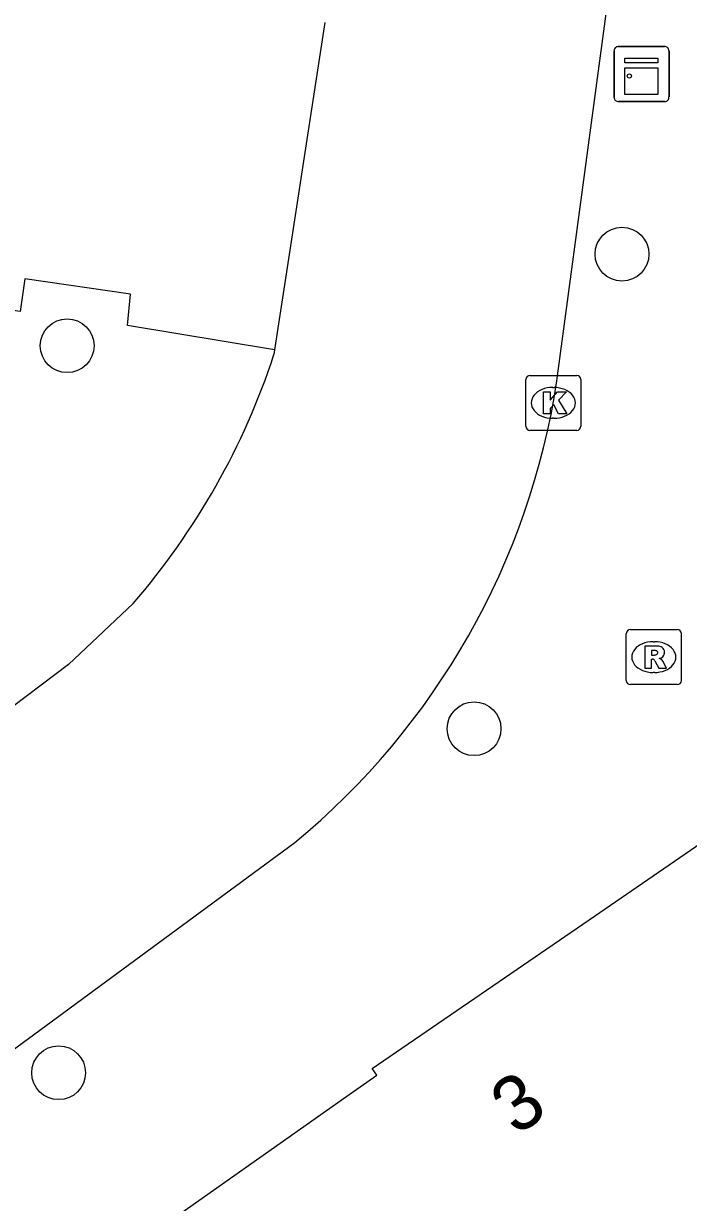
# Model space of a CAD drawing. Extents: x 160664 to 161506, y 382245 to 383288.
# Drawn here: x 160901.63 to 160913.72, y 383220.36 to 383241.8 of the extents above; entities that cross this region are included whole.
import ezdxf

# ---------------------------------------------------------------- set-up
doc = ezdxf.new("R2010")
doc.units = 0
for name, color, linetype in [('IMGEO_Boom', 7, 'Continuous'), ('IMGEO_Kast', 7, 'Continuous'), ('IMGEO_Kolk', 7, 'Continuous'), ('IMGEO_Pand', 7, 'Continuous'), ('IMGEO_Pand_nummerreeks', 7, 'Continuous'), ('IMGEO_Rijbaan_lokaal_gesloten', 7, 'Continuous'), ('IMGEO_Rijbaan_lokaal_open', 7, 'Continuous'), ('IMGEO_Rioolput', 7, 'Continuous')]:
    doc.layers.add(name, color=color, linetype=linetype)

msp = doc.modelspace()

# ---------------------------------------------------------------- linework, layer by layer
at = {"layer": 'IMGEO_Boom'}
for centre in [(160912.513, 383237.607), (160902.424, 383235.941), (160909.823, 383228.976), (160902.269, 383222.719)]:
    msp.add_circle(centre, 0.489, dxfattribs=at)
at = {"layer": 'IMGEO_Kast'}
for p, q in [((160912.443, 383241.382), (160913.284, 383241.382)), ((160913.284, 383241.382), (160912.443, 383241.382)), ((160913.368, 383241.307), (160913.368, 383240.466)), ((160913.368, 383240.466), (160913.368, 383241.307)), ((160912.368, 383240.457), (160912.368, 383241.298)), ((160912.368, 383241.298), (160912.368, 383240.457)), ((160913.293, 383240.382), (160912.452, 383240.382)), ((160912.452, 383240.382), (160913.293, 383240.382))]:
    msp.add_line(p, q, dxfattribs=at)
for points in [[(160912.563, 383241.172), (160913.163, 383241.172), (160913.163, 383241.087), (160912.563, 383241.087), (160912.563, 383241.172)], [(160912.563, 383240.997), (160913.163, 383240.997), (160913.163, 383240.508), (160912.563, 383240.508), (160912.563, 383240.997)]]:
    msp.add_lwpolyline(points, dxfattribs=at)
msp.add_circle((160912.647, 383240.846), 0.0377, dxfattribs=at)
for centre, start, end in [((160912.446, 383241.304), 92.4484, 184.2845), ((160912.446, 383241.304), 92.4484, 184.2845), ((160913.29, 383241.304), 2.4484, 94.2845), ((160913.29, 383241.304), 2.4484, 94.2845), ((160912.446, 383240.46), 182.4484, 274.2845), ((160912.446, 383240.46), 182.4484, 274.2845), ((160913.29, 383240.46), 272.4484, 4.2845), ((160913.29, 383240.46), 272.4484, 4.2845)]:
    msp.add_arc(centre, 0.0779, start, end, dxfattribs=at)
at = {"layer": 'IMGEO_Kolk'}
for p, q in [((160910.764, 383234.476), (160910.764, 383235.328)), ((160910.839, 383235.402), (160911.691, 383235.402)), ((160911.765, 383235.328), (160911.765, 383234.476)), ((160911.252, 383235.182), (160911.277, 383235.182)), ((160911.275, 383234.622), (160911.25, 383234.622)), ((160911.691, 383234.402), (160910.839, 383234.402))]:
    msp.add_line(p, q, dxfattribs=at)
for points in [[(160910.764, 383234.476), (160910.764, 383235.328)], [(160910.839, 383235.402), (160911.691, 383235.402)], [(160911.765, 383235.328), (160911.765, 383234.476)], [(160911.085, 383235.102), (160911.208, 383235.102), (160911.208, 383234.951), (160911.338, 383235.102), (160911.502, 383235.102), (160911.356, 383234.951), (160911.509, 383234.702), (160911.357, 383234.702), (160911.272, 383234.866), (160911.208, 383234.799), (160911.208, 383234.702), (160911.085, 383234.702), (160911.085, 383235.102)], [(160911.691, 383234.402), (160910.839, 383234.402)]]:
    msp.add_lwpolyline(points, dxfattribs=at)
for centre, start, end in [((160910.841, 383235.326), 91.552, 178.448), ((160910.841, 383235.326), 91.552, 178.448), ((160911.689, 383235.326), 1.552, 88.448), ((160911.689, 383235.326), 1.552, 88.448), ((160910.841, 383234.478), 181.552, 268.448), ((160910.841, 383234.478), 181.552, 268.448), ((160911.689, 383234.478), 271.552, 358.448), ((160911.689, 383234.478), 271.552, 358.448)]:
    msp.add_arc(centre, 0.0765, start, end, dxfattribs=at)
for centre, major_axis, ratio, start_param, end_param in [((160911.251, 383234.902), (-0.387, 0.002), 0.722429, 4.712389, 7.853982), ((160911.276, 383234.902), (-0.39, 0.002), 0.717154, 1.570796, 4.712389)]:
    msp.add_ellipse(centre, major_axis=major_axis, ratio=ratio, start_param=start_param, end_param=end_param, dxfattribs=at)
at = {"layer": 'IMGEO_Pand'}
msp.add_lwpolyline([(160903.028, 383219.134), (160907.507, 383222.293), (160908.052, 383222.677), (160907.969, 383222.794), (160911.914, 383225.501), (160916.477, 383228.632)], dxfattribs=at)
at = {"layer": 'IMGEO_Rijbaan_lokaal_gesloten'}
for points in [[(160911.331, 383235.302), (160912.522, 383244.195), (160912.882, 383247.022)], [(160907.107, 383241.817), (160906.197, 383235.866)], [(160906.197, 383235.866), (160906.184, 383235.781)], [(160903.622, 383231.251), (160902.449, 383230.144), (160897.372, 383226.313)], [(160900.314, 383222.312), (160906.564, 383226.907)]]:
    msp.add_lwpolyline(points, dxfattribs=at)
for centre, radius, start, end in [((160893.648, 383239.882), 13.19, 319.1309, 341.8873), ((160897.947, 383237.351), 13.54, 309.5251, 351.2958)]:
    msp.add_arc(centre, radius, start, end, dxfattribs=at)
at = {"layer": 'IMGEO_Rijbaan_lokaal_open'}
msp.add_lwpolyline([(160906.197, 383235.866), (160903.519, 383236.311), (160903.574, 383236.879), (160901.654, 383237.155), (160901.569, 383236.562), (160900.782, 383236.68)], dxfattribs=at)
at = {"layer": 'IMGEO_Rioolput'}
for p, q in [((160912.591, 383229.852), (160912.591, 383230.704)), ((160912.666, 383230.778), (160913.518, 383230.778)), ((160913.592, 383230.704), (160913.592, 383229.852)), ((160913.079, 383230.558), (160913.104, 383230.558)), ((160913.102, 383229.998), (160913.077, 383229.998)), ((160913.518, 383229.778), (160912.666, 383229.778))]:
    msp.add_line(p, q, dxfattribs=at)
for points in [[(160912.591, 383229.852), (160912.591, 383230.704)], [(160912.666, 383230.778), (160913.518, 383230.778)], [(160913.592, 383230.704), (160913.592, 383229.852)], [(160913.18, 383230.476), (160912.928, 383230.478), (160912.928, 383230.078)], [(160913.106, 383230.397), (160913.052, 383230.397), (160913.052, 383230.316)], [(160912.928, 383230.078), (160913.052, 383230.078), (160913.052, 383230.24), (160913.063, 383230.24)], [(160913.052, 383230.316), (160913.104, 383230.316)], [(160913.11, 383230.211), (160913.181, 383230.078), (160913.321, 383230.078), (160913.256, 383230.204)], [(160913.518, 383229.778), (160912.666, 383229.778)]]:
    msp.add_lwpolyline(points, dxfattribs=at)
for centre, radius, start, end in [((160912.668, 383230.702), 0.0765, 91.552, 178.448), ((160912.668, 383230.702), 0.0765, 91.552, 178.448), ((160913.516, 383230.702), 0.0765, 1.552, 88.448), ((160913.516, 383230.702), 0.0765, 1.552, 88.448), ((160913.112, 383230.301), 0.0964, 77.0061, 93.1865), ((160913.126, 383230.358), 0.0378, 276.6634, 79.6772), ((160913.179, 383230.366), 0.109, 350.3612, 89.416), ((160913.062, 383230.187), 0.0533, 26.0293, 88.6989), ((160913.088, 383230.505), 0.19, 274.7715, 282.9687), ((160913.177, 383230.366), 0.112, 277.5842, 350.9817), ((160913.161, 383230.151), 0.108, 29.5134, 73.7905), ((160912.668, 383229.854), 0.0765, 181.552, 268.448), ((160912.668, 383229.854), 0.0765, 181.552, 268.448), ((160913.516, 383229.854), 0.0765, 271.552, 358.448), ((160913.516, 383229.854), 0.0765, 271.552, 358.448)]:
    msp.add_arc(centre, radius, start, end, dxfattribs=at)
for centre, major_axis, ratio, start_param, end_param in [((160913.078, 383230.278), (-0.387, 0.002), 0.722429, 4.712389, 7.853982), ((160913.103, 383230.278), (-0.39, 0.002), 0.717154, 1.570796, 4.712389)]:
    msp.add_ellipse(centre, major_axis=major_axis, ratio=ratio, start_param=start_param, end_param=end_param, dxfattribs=at)

# ---------------------------------------------------------------- texts
at = {"layer": 'IMGEO_Pand_nummerreeks'}
msp.add_text('3', height=1, rotation=34.4577, dxfattribs=at).set_placement((160910.589, 383221.56))

doc.saveas('drawing.dxf')
